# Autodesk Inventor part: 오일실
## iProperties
Created: 2009-02
Part Number: 오일실
Material: 고무
Description: 오일-실
Document SubType Name: Modeling
Standard: KS B 2804
Designer: SeoGD™
Standards Organization: KS
Language: ko-KR
Size Designation: D - 10 20 7
Categories: <MemberInstance><Categories><Category DisplayName="샤프트 부품" InternalName="7f7aeb1f-a693-4053-b835-cee3144e0d98" Mnemonic="SHFT"><Category DisplayName="실링" Intern
Density: 0.93 g/cm^3
IsCustomPart: 0
Author: SeoGD™
